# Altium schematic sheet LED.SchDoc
size B
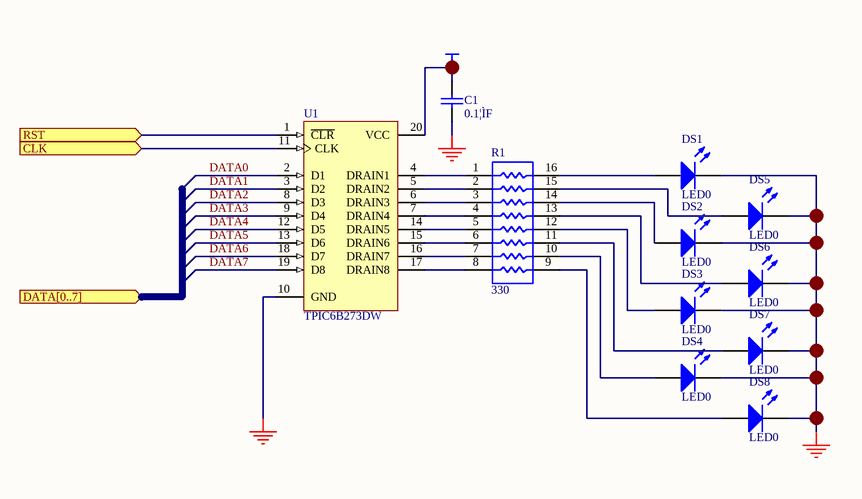
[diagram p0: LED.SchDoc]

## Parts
C1  0.1¦ÌF  [RAD-0.3]
DS1  LED0  [LED-0]
DS2  LED0  [LED-0]
DS3  LED0  [LED-0]
DS4  LED0  [LED-0]
DS5  LED0  [LED-0]
DS6  LED0  [LED-0]
DS7  LED0  [LED-0]
DS8  LED0  [LED-0]
R1  330  [SO-G16/G6.9]
U1  TPIC6B273DW  [SO-G20/G7.1]

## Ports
CLK (in), DATA[0..7] (in), RST (in)

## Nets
GND: C1.1 DS1.2(K) DS2.2(K) DS3.2(K) DS4.2(K) DS5.2(K) DS6.2(K) DS7.2(K) DS8.2(K) U1.10(GND)
VCC: C1.2 U1.20(VCC)
CLK: U1.11(CLK) ; port CLK
DATA0: U1.2(D1)
DATA1: U1.3(D2)
DATA2: U1.8(D3)
DATA3: U1.9(D4)
DATA4: U1.12(D5)
DATA5: U1.13(D6)
DATA6: U1.18(D7)
DATA7: U1.19(D8)
RST: U1.1(~{CLR}) ; port RST
NetDS1_1: DS1.1(A) R1.16
NetDS2_1: DS2.1(A) R1.14
NetDS3_1: DS3.1(A) R1.12
NetDS4_1: DS4.1(A) R1.10
NetDS5_1: DS5.1(A) R1.15
NetDS6_1: DS6.1(A) R1.13
NetDS7_1: DS7.1(A) R1.11
NetDS8_1: DS8.1(A) R1.9
NetR1_1: R1.1 U1.4(DRAIN1)
NetR1_2: R1.2 U1.5(DRAIN2)
NetR1_3: R1.3 U1.6(DRAIN3)
NetR1_4: R1.4 U1.7(DRAIN4)
NetR1_5: R1.5 U1.14(DRAIN5)
NetR1_6: R1.6 U1.15(DRAIN6)
NetR1_7: R1.7 U1.16(DRAIN7)
NetR1_8: R1.8 U1.17(DRAIN8)

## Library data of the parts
C1 = Cap: Capacitor; Manufacturer: Generic Components; Class I: Passive
DS1-DS8 = LED0: Typical INFRARED GaAs LED; Manufacturer: Generic Components; Class I: Optoelectronic
R1 = Res Pack3: Resistor Array; Manufacturer: Generic Components; Class I: Passive
U1 = TPIC6B273DW: Power Logic Octal D-Type Latch; Manufacturer: Texas Instruments; Package Information: Latest Revision: Dec-1998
